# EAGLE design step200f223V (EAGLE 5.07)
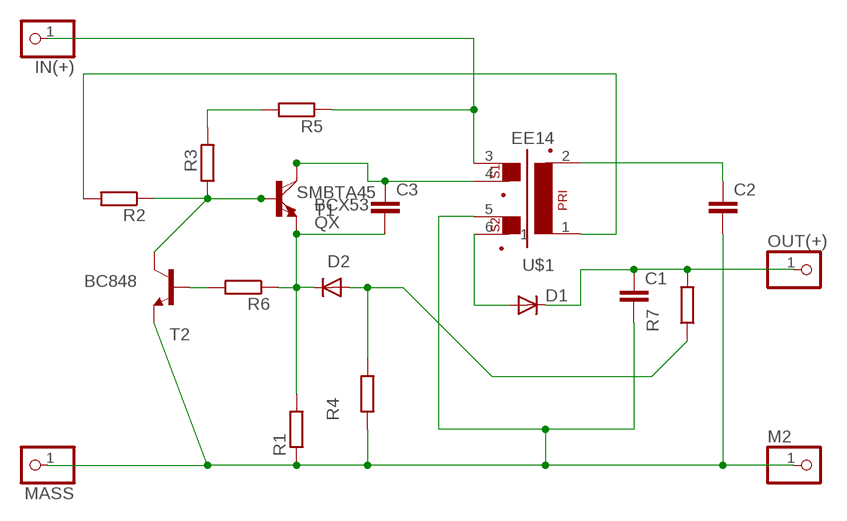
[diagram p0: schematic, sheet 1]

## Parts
C1  C-EU050-025X075  [C050-025X075]
C2  C-EUC0805  [C0805]
C3  C-EU025-024X044  [C025-024X044]
D1  DIODE-SMA-DO214  [SMA-DO214AC]
D2  DIODE-MINIMELF  [MINIMELF]
IN(+)  PINHD-1X11MM6  [1X1MM8]
M2  PINHD-1X11MM6  [1X1MM8]
MASS  PINHD-1X11MM6  [1X1MM8]
OUT(+)  PINHD-1X11MM6  [1X1MM8]
QX  BCX53  [SOT223]
R1  R-EU_R1206  [R1206]
R2  R-EU_R0805  [R0805]
R3  R-EU_R1206  [R1206]
R4  R-EU_R1206  [R1206]
R5  R-EU_R1206  [R1206]
R6  R-EU_R0805  [R0805]
R7  R-EU_R1206  [R1206]
T1  SMBTA45  BC848  [SOT23]
T2  BC848  [SOT23]
U$1  EE14  [EE14]

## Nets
A: D1.A U$1.6
B1C2: QX.1(B) R2.1 R3.1 T1.B T2.C
C1: C3.1 QX.2(C) T1.C U$1.4
EB: C3.2 D2.C QX.3(E) R1.2 R6.1 T1.E
N$1: R3.2 R5.2
N$2: R6.2 T2.B
N$3: D2.A R4.2 R7.1
N$4: R2.2 U$1.1
N$6: C2.1 U$1.2
V+: IN(+).1 R5.1 U$1.3
V-: C1.2 C2.2 M2.1 MASS.1 R1.1 R4.1 T2.E U$1.5
VOUT+: C1.1 D1.K(C) OUT(+).1 R7.2

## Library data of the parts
C1-C3 = rcl:C-EU: CAPACITOR, European symbol
D1 D2 = diode:DIODE-: DIODE
IN(+) M2 MASS OUT(+) = pinhead:PINHD-1X1: PIN HEADER
QX = transistor-power:BCX53
R1-R7 = rcl:R-EU_: RESISTOR, European symbol
T1 T2 = transistor:BC848: NPN TRANSISTOR
U$1 = trafo:EE14

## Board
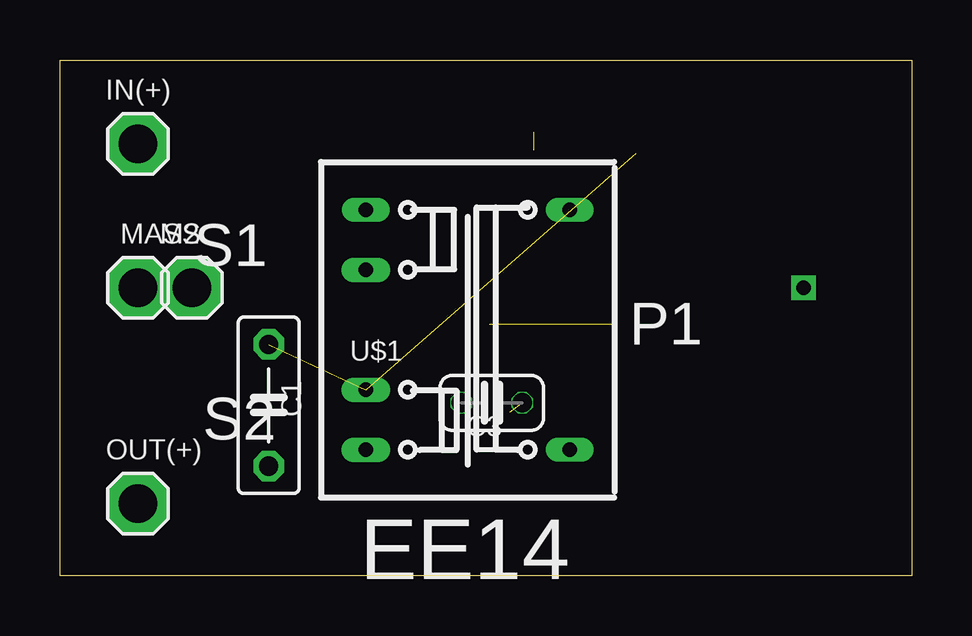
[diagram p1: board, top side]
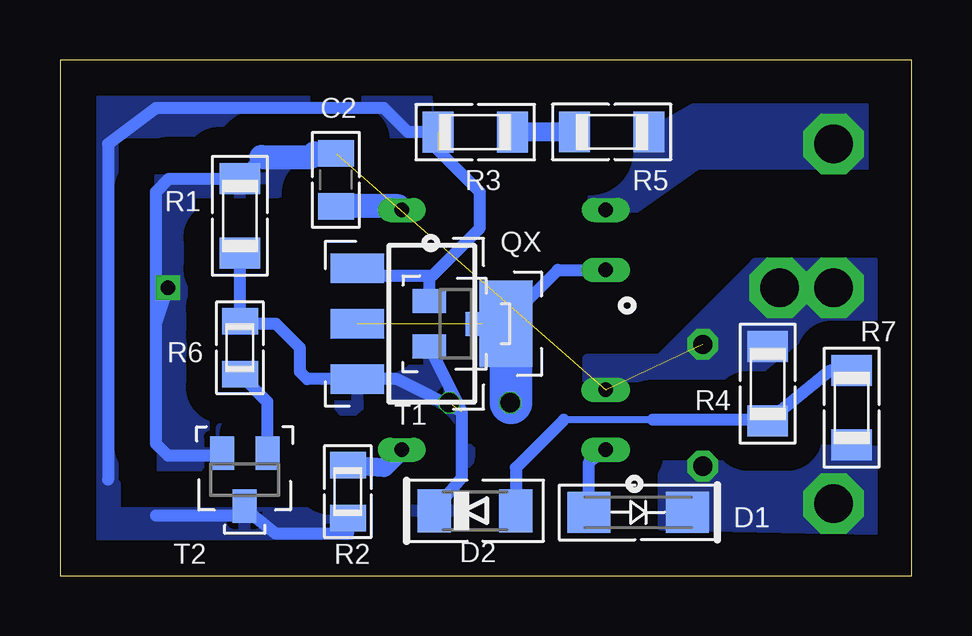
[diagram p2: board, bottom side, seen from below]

Size 35.5 x 21.5 mm. Coordinates in mm from the lower left corner, seen from the top.
Outline: 0,21.5 35.5,21.5 35.5,0 0,0 0,21.5
Copper layers (1*16): Top 0.035mm / dielectric 1.5mm / Bottom 0.035mm
Design rules "default": minimum track width 10mil, minimum drill 20mil, track to track 8mil, track to pad 8mil, pad to pad 8mil, via to via 8mil, smd to smd 8mil, copper to edge 40mil, drill to drill 8mil, minimum pad ring 1mil, minimum via ring 8mil, stop-mask expansion 4mil, vias tented up to drill 0mil, thermal gap 10mil

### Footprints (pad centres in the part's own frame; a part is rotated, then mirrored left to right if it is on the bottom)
C050-025X075 = drill 0.8 pad 1.27 octagon: 1 -2.54,0; 2 2.54,0
C0805 = smd 1.1 x 1.5: 1 -1.1,0; 2 1.1,0
C025-024X044 = drill 0.813 octagon: 1 -1.27,0; 2 1.27,0
SMA-DO214AC = smd 1.8 x 1.7: A 2.05,-0.127; K -2.05,-0.127
MINIMELF = smd 1.4 x 1.8: A 1.7,0; C -1.7,0
1X1MM8 = drill 1.6 pad 2.54 octagon: 1 0,0
SOT223 = smd 1.219 x 2.235: 1 -2.311,-3.099; 2 0,-3.099; 3 2.311,-3.099 | smd 3.6 x 2.2: 4 0,3.099
R1206 = smd 1.3 x 1.7: 1 -1.55,0; 2 1.55,0
R0805 = smd 1.1 x 1.5: 1 -1.1,0; 2 1.1,0
SOT23 = smd 1 x 1.4: B -0.95,-1.1; C 0,1.1; E 0.95,-1.1
EE14 = drill 0.6 pad 1 long: 1 4.25,-5; 2 4.25,5; 3 -4.25,5 | drill 0.6 pad 1.016 long: 4 -4.25,2.5; 5 -4.25,-2.5; 6 -4.25,-5

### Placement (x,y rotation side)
C1  8.7,7.1 90 top
C2  24,16.5 90 bottom
C3  18,7.2 0 top
D1  11.39,2.51 180 bottom
D2  18.2,2.7 0 bottom
IN(+)  3.25,18 0 top
M2  5.5,12 0 top
MASS  3.25,12 0 top
OUT(+)  3.25,3 0 top
QX  20,10.5 270 bottom
R1  28,15 270 bottom
R2  23.5,3.5 90 bottom
R3  18.19,18.49 0 bottom
R4  6,8 270 bottom
R5  12.5,18.5 180 bottom
R6  28,9.5 270 bottom
R7  2.5,7 270 bottom
T1  19,10.5 270 bottom
T2  27.8,4 180 bottom
U$1  17,10.25 0 top

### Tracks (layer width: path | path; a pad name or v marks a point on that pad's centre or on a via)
A
  Bottom 0.5: U$1.6 13.45,4.75 D1.A
B1C2  (1 unrouted)
  Bottom 0.5: 19.74,17.74 18,16 18,14.5 20,12.5 | 20,12.5 22.79,12.5 QX.1 | R3.1 20.99,18.49 22,19.5 31.5,19.5 33.5,18 33.5,4 | 31.5,2.5 28.2,2.5 T2.C 27.8,2.8 26.5,1.75 23.5,1.75 R2.1 | T1.B 20.1,12.4 20,12.5
  pour Bottom (isolate 1.5): 20.2,20 34.4,20 34.4,1.1 23.3,1.1 23.3,1.2 23.2,1.2 23.2,2.6 33.2,2.6 33.2,3.8 33.3,3.8 33.3,18.5 20.1,18.5
C1  (1 unrouted)
  Bottom 0.5: U$1.4 14.75,12.75 17,10.5 T1.C | C3.1 16.7,7.2
  Bottom 1: 16.7,9.6 17,10.5
  Bottom 1.778: 16.7,7.2 16.7,9.6
EB  (1 unrouted)
  Bottom 0.5: R6.1 28,10.5 | R6.1 R1.2 | R6.1 27.9,10.5 26.5,10.5 25.5,9.5 25.5,8.5 25.19,8.19 QX.3 21.46,8.19 18.75,6.83 | 18.75,6.83 T1.E | D2.C 18.75,4.1 18.75,6.83
  pour Bottom (isolate 1.5, rank 2): 16.2,2.1 20.6,2.1 20.6,6.4 21.1,6.9 23.7,6.9 24.5,7.7 24.5,8.2 24,8.7 21.2,8.7 20.3,9.6 18.7,9.6 17.8,8.7 17.8,4.6 17.6,4.4 16.2,4.4 15.8,4
N$1
  Bottom 0.8: R5.2 15.63,18.5 R3.2
N$2
  Bottom 0.5: T2.B 26.85,7.25 R6.2
N$3
  Bottom 0.3: 10.8,6.5 14.5,6.5
  Bottom 0.5: D2.A 16.5,4.5 14.5,6.5 | R7.1 3.4,8.55 R4.2 6,6.5 10.8,6.5
N$4
  Bottom 0.8: R2.2 22,4.5 U$1.1
N$6
  Bottom 1: C2.1 21.4,15.4 U$1.2
V+
  pour Bottom (isolate 1.8, rank 4, no thermals): 0.96,20.54 7.46,20.54 12.1,17.9 13.1,18.04 13.5,15.1 11.43,15.24 8.89,17.04 0.96,17.04
V-  (via drill 0.6)  (2 unrouted)
  Bottom 0.5: 31.5,10.5 31.5,5.5 31,5 28.85,5 T2.E | 31.5,10.5 31.5,16 30.95,16.55 R1.1 27.1,17.45 | 31.5,10.5 v31,12
  Bottom 1: 27.1,17.45 25.05,17.45 24.9,17.6 C2.2
  pour Bottom (isolate 1.422, no thermals): 1.5,13 6.5,13 10.5,9 13.5,9 13.5,7 9,7 7.5,8.5 3.5,8.5 1.5,10.5
  pour Bottom (isolate 1.5, rank 2): 23.5,18.3 30.6,18.3 32.6,16.3 32.6,4.7 32.4,4.5 28.6,4.5 28.5,4.4 28.5,6.5 28.6,6.6 29.4,6.6 30.1,7.3 30.1,15.9 30,16 26.4,16 25.7,16.7 23.8,16.7 23.5,17
VOUT+
  pour Bottom (isolate 1.422, rank 3, no thermals): 1.4,5.3 10,5.5 10.5,5 10.5,2 1.4,1.8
